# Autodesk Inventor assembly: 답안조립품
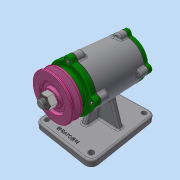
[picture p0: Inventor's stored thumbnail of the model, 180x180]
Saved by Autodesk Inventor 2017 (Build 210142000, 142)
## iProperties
Part Number: 답안조립품
Material: 일반
Document SubType Name: Assembly
Designer: MRC
Author: MRC
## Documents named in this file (12)
- C:\Users\MRC\Desktop\720716V1006\답안조립품.iam
- C:\Users\MRC\Desktop\720716V1006\본체.ipt
- C:\Users\MRC\Desktop\720716V1006\개스킷.ipt
- C:\Users\MRC\Desktop\720716V1006\앞커버.ipt
- C:\Users\MRC\Desktop\720716V1006\뒤커버.ipt
- C:\Users\MRC\Desktop\720716V1006\베어링 6204.ipt
- C:\Users\MRC\Desktop\720716V1006\오일 실.ipt
- C:\Users\MRC\Desktop\720716V1006\축.ipt
- C:\Users\MRC\Desktop\720716V1006\볼트 M4 x 12.ipt
- C:\Users\MRC\Desktop\720716V1006\키 4 x 4.ipt
- C:\Users\MRC\Desktop\720716V1006\V-벨트풀리.ipt
- C:\Users\MRC\Desktop\720716V1006\너트 M12 x 1.25.ipt
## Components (3 placed, 2 different names)
1. 개스킷:1
2. 개스킷:2
3. V-벨트풀리:1
